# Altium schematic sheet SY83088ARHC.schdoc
size 127 x 101 mm
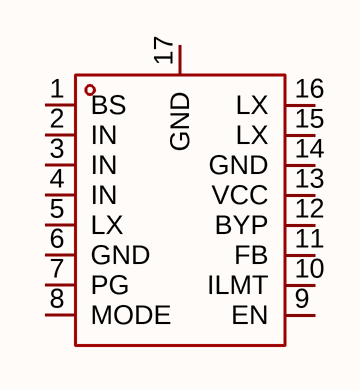
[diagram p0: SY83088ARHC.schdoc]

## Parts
U?  sy83088arhc  [QFN-16_L2.5-W2.5-P0.45-TL-EP0.6]  (value not drawn)

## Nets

Not connected (* = marked no-connect by the designer): U? 1(BS) 2(IN) 3(IN) 4(IN) 5(LX) 6(GND) 7(PG) 8(MODE) 9(EN) 10(ILMT) 11(FB) 12(BYP) 13(VCC) 14(GND) 15(LX) 16(LX) 17(GND)

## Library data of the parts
U? = sy83088arhc: 功能类型:降压型;工作电压:4V~24V;输出电压:600mV~12.5V;输出电流:8A;输出类型:可调;; Manufacturer: Silergy(矽力杰); AddInBom: yes; ModelId: d6724371409549c497c9b62ea056431f; ModelTransform: 98.504,98.504,0,0,0,0,0,0,0; Function: 降压型; Voltage - Supply: 4V~24V; Output Current: 8A; Frequency - Switching: 600kHz; Synchronous Rectifier: 是; Number of Outputs: 1; Topology: 降压式; Quiescent Current: 160uA; Output Type: 可调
